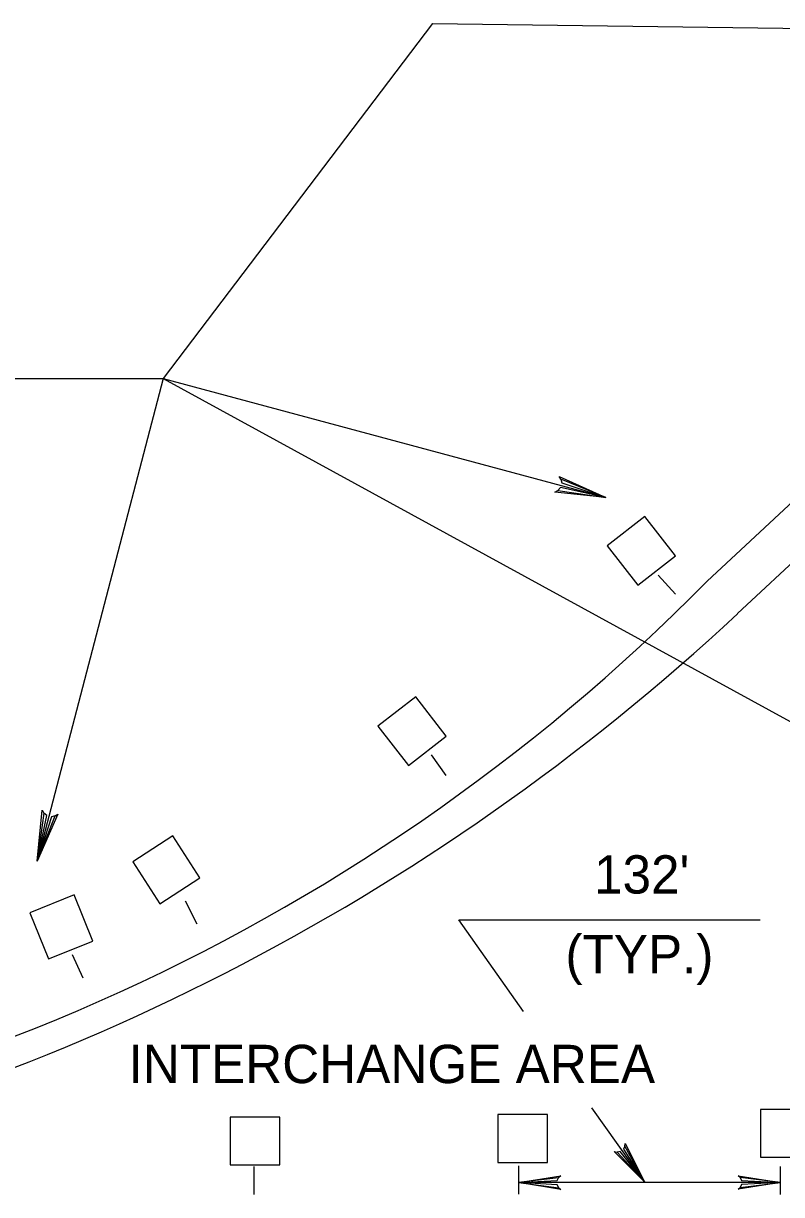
# Model space of a CAD drawing. Extents: x 640253 to 641999, y 298458 to 299646.
# Drawn here: x 641425.1 to 641484.5, y 299424 to 299515.7 of the extents above; entities that cross this region are included whole.
import ezdxf

# ---------------------------------------------------------------- set-up
doc = ezdxf.new("R2010")
doc.units = 0
doc.layers.add('2', color=7, linetype='Continuous')

msp = doc.modelspace()

# ---------------------------------------------------------------- linework, layer by layer
at = {"layer": '2'}
for p, q in [((641457.171, 299515.743), (641436.084, 299487.935)), ((641457.171, 299515.743), (641518.29, 299514.933)), ((641478.681, 299472.06), (641509.056, 299500.387)), ((641481.042, 299469.526), (641511.434, 299497.854)), ((641436.084, 299487.935), (641426.211, 299450.139)), ((641436.084, 299487.935), (641470.748, 299478.62)), ((641436.084, 299487.935), (641488.371, 299459.326)), ((641476.181, 299471.037), (641474.844, 299472.529)), ((641458.233, 299456.839), (641457.088, 299458.47)), ((641438.725, 299445.21), (641437.823, 299446.997)), ((641459.215, 299445.558), (641482.814, 299445.558)), ((641464.297, 299438.379), (641459.215, 299445.558)), ((641429.821, 299440.991), (641428.988, 299442.795)), ((641473.752, 299425.022), (641469.64, 299430.831)), ((641443.202, 299424.033), (641443.202, 299426.237)), ((641463.914, 299424.068), (641463.914, 299426.273)), ((641484.409, 299424.033), (641484.409, 299426.237)), ((641484.409, 299424.97), (641463.892, 299424.97))]:
    msp.add_line(p, q, dxfattribs=at)
for points in [[(641423.21, 299487.935), (641436.084, 299487.935)], [(641467.217, 299480.062), (641467.281, 299479.76), (641470.748, 299478.62), (641467.217, 299480.062), (641467.073, 299480.272), (641470.748, 299478.62), (641467.186, 299479.391), (641466.988, 299479.164), (641470.748, 299478.62), (641466.742, 299479.041), (641466.988, 299479.164)], [(641427.627, 299453.681), (641427.325, 299453.612), (641426.211, 299450.139), (641427.627, 299453.681), (641427.836, 299453.827), (641426.211, 299450.139), (641426.956, 299453.706), (641426.727, 299453.904), (641426.211, 299450.139), (641426.604, 299454.147), (641426.727, 299453.904)], [(641472.228, 299427.82), (641472.125, 299427.591), (641473.752, 299425.022), (641472.228, 299427.82), (641472.258, 299428.026), (641473.752, 299425.022), (641471.87, 299427.399), (641471.616, 299427.349), (641473.752, 299425.022), (641471.396, 299427.398), (641471.616, 299427.349)], [(641467.05, 299424.57), (641466.929, 299424.795), (641463.892, 299424.97), (641467.05, 299424.57), (641467.206, 299424.433), (641463.892, 299424.97), (641466.929, 299425.127), (641467.033, 299425.351), (641463.892, 299424.97), (641467.206, 299425.491), (641467.033, 299425.351)], [(641481.25, 299425.37), (641481.371, 299425.145), (641484.409, 299424.97), (641481.25, 299425.37), (641481.094, 299425.508), (641484.409, 299424.97), (641481.371, 299424.814), (641481.267, 299424.589), (641484.409, 299424.97), (641481.094, 299424.449), (641481.267, 299424.589)]]:
    msp.add_lwpolyline(points, dxfattribs=at)
for points in [[(641476.19, 299474.062), (641473.794, 299477.133), (641470.836, 299474.833), (641473.231, 299471.758)], [(641458.244, 299459.935), (641455.848, 299463.006), (641452.89, 299460.706), (641455.285, 299457.631)], [(641438.954, 299448.849), (641436.836, 299452.116), (641433.688, 299450.083), (641435.806, 299446.812)], [(641430.563, 299443.885), (641429.102, 299447.497), (641425.627, 299446.097), (641427.086, 299442.483)], [(641441.311, 299426.351), (641445.209, 299426.351), (641445.209, 299430.099), (641441.311, 299430.099)], [(641462.281, 299426.554), (641466.179, 299426.554), (641466.179, 299430.302), (641462.281, 299430.302)], [(641482.85, 299426.956), (641486.748, 299426.956), (641486.748, 299430.704), (641482.85, 299430.704)]]:
    msp.add_lwpolyline(points, close=True, dxfattribs=at)
for centre, radius, start, end in [((641368.281, 299580.998), 155.099, 272.37756, 315.38102), ((641360.297, 299598.993), 177.042, 281.18464, 313.00346)]:
    msp.add_arc(centre, radius, start, end, dxfattribs=at)

# ---------------------------------------------------------------- texts
for s, p in [("132'", (641469.815, 299447.604)), ('(TYP.)', (641467.574, 299441.357)), ('INTERCHANGE AREA', (641433.361, 299432.76))]:
    msp.add_text(s, height=3, dxfattribs=at).set_placement(p)

doc.saveas('drawing.dxf')
